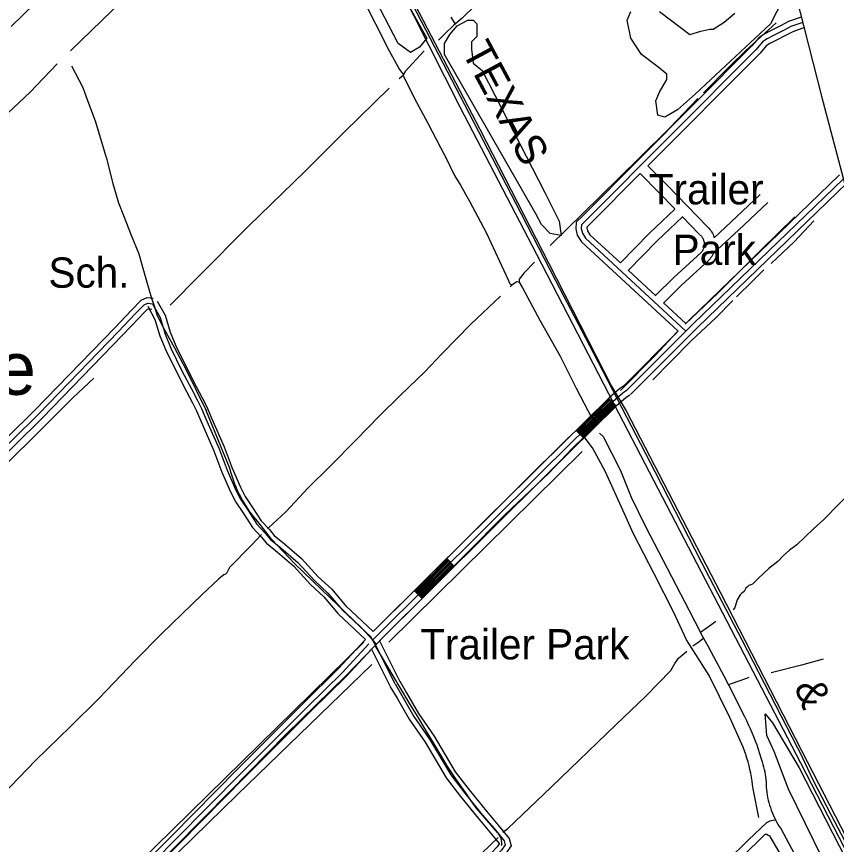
# Model space of a CAD drawing. Extents: x 3297772 to 3335630, y 634068 to 659439.
# Drawn here: x 3313452 to 3315700, y 643022 to 645293 of the extents above; entities that cross this region are included whole.
import ezdxf

# ---------------------------------------------------------------- set-up
doc = ezdxf.new("R2010")
doc.units = 0
for name, color, linetype in [('V-BLDG-IDEN', 7, 'Continuous'), ('V-DTCH-CNTR', 7, 'Continuous'), ('V-RAIL-IDEN', 7, 'Continuous'), ('V-RAIL-TRAK', 7, 'Continuous'), ('V-ROAD-CNTR', 7, 'Continuous'), ('V-SITE-VEGE', 7, 'Continuous'), ('V-TOPO-GNAM-IDEN', 7, 'Continuous'), ('V-TOPO-SHOR', 7, 'Continuous')]:
    doc.layers.add(name, color=color, linetype=linetype)

msp = doc.modelspace()

# ---------------------------------------------------------------- linework, layer by layer
at = {"layer": 'V-DTCH-CNTR'}
msp.add_line((3314037.2, 644051.3), (3313971.4, 644212.6), dxfattribs=at)
for points in [[(3313697.9, 644905.6), (3313668.8, 645003.6), (3313643.6, 645072), (3313634.5, 645097.6), (3313603.2, 645156.9)], [(3313697.9, 644905.6), (3313701.1, 644893), (3313715.3, 644835.5), (3313731.6, 644781.6), (3313745.2, 644747.5), (3313766.4, 644693), (3313786.8, 644642.5), (3313797.8, 644602.4), (3313808.8, 644564.6), (3313822.2, 644520.5), (3313828.8, 644499.4), (3313837.7, 644473.2), (3313855.4, 644437.8), (3313884.6, 644384.5), (3313915.6, 644325.6), (3313971.4, 644212.6)], [(3315086.3, 644217.3), (3315032.6, 644163.6), (3315008.4, 644139.9), (3314976, 644108), (3314912, 644040.9), (3314792.2, 643926.7), (3314683.8, 643818.1), (3314554, 643687), (3314461.3, 643595), (3314439, 643571.8), (3314435.3, 643568), (3314355.1, 643484.8), (3314191.5, 643324.4), (3314037.1, 643168), (3313883.6, 643012.5), (3313726.6, 642851.1), (3313565.2, 642696.4), (3313438.4, 642575.1), (3313397.1, 642535.1)], [(3315487.9, 643095.9), (3315471.8, 643174.8), (3315470.5, 643185.4), (3315469, 643196.1), (3315467.2, 643206.6), (3315465.2, 643217.2), (3315463, 643227.7), (3315460.6, 643238.1), (3315457.9, 643248.5), (3315455, 643258.9), (3315451.8, 643269.1), (3315448.5, 643279.3), (3315444.9, 643289.4), (3315407.7, 643370.5), (3315350.9, 643485.8), (3315315, 643542.8), (3315289.5, 643583.8), (3315254.4, 643658.1), (3315200.8, 643764.1), (3315143.9, 643874), (3315106.1, 643957.3), (3315066, 644045.7), (3315031.2, 644110.1), (3315008.4, 644139.9)], [(3314439, 643571.8), (3314398.1, 643616), (3314310.5, 643699.6), (3314214.6, 643791.6), (3314150.5, 643859.2), (3314113.2, 643908.1), (3314107.6, 643914.6), (3314102.1, 643921.2), (3314096.8, 643928), (3314091.6, 643934.9), (3314086.7, 643942), (3314081.9, 643949.1), (3314077.3, 643956.4), (3314072.9, 643963.8), (3314068.6, 643971.3), (3314064.6, 643978.9), (3314060.8, 643986.6), (3314057.1, 643994.4), (3314053.7, 644002.3), (3314050.4, 644010.3), (3314047.4, 644018.3), (3314044.5, 644026.5), (3314041.9, 644034.7), (3314039.5, 644042.9), (3314037.2, 644051.3)], [(3314712.6, 643122.8), (3314698.9, 643141.7), (3314685.3, 643160.7), (3314671.9, 643179.8), (3314658.7, 643199.1), (3314645.8, 643218.5), (3314633, 643238.1), (3314620.5, 643257.8), (3314597.6, 643296.6), (3314574.5, 643335.3), (3314551.2, 643374), (3314527.9, 643412.5), (3314504.3, 643450.9), (3314435.3, 643568)], [(3314781.9, 643019.3), (3314782.2, 643022.2), (3314782.3, 643025.2), (3314782.2, 643028.2), (3314781.9, 643031.1), (3314781.4, 643034.1), (3314780.7, 643037), (3314779.8, 643039.8), (3314778.7, 643042.6), (3314777.4, 643045.3), (3314775.9, 643047.9), (3314774.3, 643050.4), (3314772.5, 643052.7), (3314770.6, 643055), (3314712.6, 643122.8)], [(3315312.5, 642860.8), (3315505.1, 643050.1), (3315509.2, 643050.1), (3315513.2, 643047.4), (3315517.2, 643046), (3315597.9, 642905.9)]]:
    msp.add_lwpolyline(points, dxfattribs=at)
at = {"layer": 'V-RAIL-TRAK'}
for points in [[(3313378, 647568.6), (3313502.7, 647328.1), (3313556.5, 647223), (3313663.7, 647016.1), (3313780.7, 646791.6), (3313880.9, 646597.2), (3313992.5, 646380), (3314088, 646196.7), (3314189.3, 645999.9), (3314301.2, 645783.7), (3314422.3, 645549.8), (3314549.9, 645303.5), (3314680.4, 645051.8), (3314820.1, 644782), (3314930.2, 644568.7), (3315033.1, 644371.8)], [(3315033.1, 644371.8), (3315202.3, 644044.8), (3315330.7, 643795.6), (3315441.2, 643583), (3315533.5, 643404.1), (3315608.5, 643259.1)], [(3315752.3, 642976.7), (3315686, 643103.7), (3315637, 643198.2), (3315608.5, 643259.1)]]:
    msp.add_lwpolyline(points, dxfattribs=at)
at = {"layer": 'V-ROAD-CNTR'}
for p, q in [((3315096.8, 644224.3), (3315075.8, 644245.7)), ((3315007.7, 644136.6), (3314986.7, 644158)), ((3314652.5, 643784.8), (3314631.4, 643806.1)), ((3314563.8, 643696.7), (3314542.7, 643718))]:
    msp.add_line(p, q, dxfattribs=at)
for points in [[(3314976.6, 647123.5), (3315026.3, 647049.2), (3315058.9, 646995.3), (3315083.1, 646954.2), (3315131.1, 646872.2), (3315155.3, 646820), (3315185.8, 646745.9), (3315213.3, 646677.8), (3315248.8, 646578.1), (3315279.5, 646485.7), (3315298.8, 646424.2), (3315330.9, 646312.4), (3315355, 646229.2), (3315394.6, 646089.2), (3315438.8, 645925), (3315553.7, 645492), (3315659.6, 645074.5), (3315735.3, 644787.8), (3315931.6, 644028.1), (3316169.6, 643125.7), (3316453.9, 642053.7)], [(3313974.6, 646363.6), (3314014.1, 646290.1), (3314141.9, 646031.1), (3314156.9, 645987.8), (3314147.2, 645961), (3314122.4, 645944.1), (3313989.9, 645810.7), (3313710.1, 645532.9), (3313567, 645393.2), (3313436.9, 645265.3)], [(3316343.5, 641851.4), (3316234, 642021.3), (3315602.3, 643244.8), (3315104.5, 644203.1), (3314879, 644639.9), (3314668.2, 645044.7), (3314541.1, 645295.8), (3314400.3, 645563.5), (3314262.3, 645829.4), (3314167.7, 646014.6), (3314033.2, 646275.1)], [(3314291.1, 645810.9), (3314532.6, 645348.2), (3314722.5, 644984.4), (3314911.8, 644615.5), (3315083.1, 644279.1), (3315123.8, 644211.7), (3315381.2, 643713.7), (3315604.6, 643279.8), (3316205.3, 642114), (3316321, 641892.3), (3316475.5, 641594.6), (3316530.5, 641494.3), (3316908.1, 640765.9), (3317235.2, 640123.1), (3317563.4, 639492.7), (3317577.5, 639465.5)], [(3315603.4, 645290.9), (3315569.3, 645279.2), (3315548.6, 645268.4), (3315520.9, 645254.4), (3315502.6, 645244.9), (3315487.8, 645235.1), (3315468.7, 645212.7), (3315004.7, 644746.8), (3314986.9, 644728.8), (3314985.4, 644710.8), (3314989.6, 644693.3), (3315000.7, 644675.4), (3315266.1, 644429.7)], [(3315608.3, 645276.8), (3315575.3, 645265.3), (3315555.4, 645255.1), (3315527.8, 645241.1), (3315510.2, 645231.9), (3315497.9, 645223.8), (3315479.8, 645202.5), (3315015.4, 644736.2), (3315001.4, 644722.1), (3315000.6, 644712), (3315003.6, 644699.2), (3315012.4, 644685), (3315287.7, 644430.2)], [(3315613.2, 645262.6), (3315581.2, 645251.5), (3315562.3, 645241.7), (3315534.6, 645227.7), (3315517.8, 645219), (3315507.9, 645212.4), (3315490.8, 645192.3), (3315183.1, 644883.3)], [(3315162.3, 644862.4), (3315026, 644725.6), (3315015.9, 644715.5), (3315015.7, 644713.1), (3315017.7, 644705), (3315024.1, 644694.7), (3315107.7, 644617.2)], [(3315162.1, 644862.4), (3315214.6, 644809.4), (3315257.1, 644765.4)], [(3315183.4, 644883.5), (3315236, 644830.4), (3315345.6, 644717.1)], [(3315124.7, 644266.9), (3315308.7, 644451.2), (3315719.5, 644847.6)], [(3315287.3, 644451), (3315298.1, 644461.9), (3315709.1, 644858.4)], [(3315135.3, 644256.3), (3315319.2, 644440.5), (3315729.9, 644836.8)], [(3315365.2, 644686.4), (3315411.1, 644729.1), (3315491.6, 644804.5)], [(3315362.3, 644642.9), (3315431.6, 644707.2), (3315512.1, 644782.6)], [(3315257.5, 644765), (3315187.8, 644699), (3315108, 644617.6)], [(3315278.3, 644743.4), (3315208.8, 644677.6), (3315129.4, 644596.6)], [(3315277.6, 644744.2), (3315324.1, 644696.2)], [(3315344.8, 644717.8), (3315347.5, 644715.4), (3315350.5, 644712.4), (3315353.2, 644709.3), (3315355.7, 644706), (3315358, 644702.5), (3315360.1, 644698.9), (3315362, 644695.2), (3315363.6, 644691.3), (3315364.9, 644687.4), (3315365.2, 644686.2)], [(3315324.9, 644695.4), (3315326.9, 644693.6), (3315328.5, 644692), (3315329.9, 644690.3), (3315331.3, 644688.6), (3315332.5, 644686.7), (3315333.6, 644684.8), (3315334.6, 644682.8), (3315335.5, 644680.7), (3315336.2, 644678.6), (3315336.8, 644676.5), (3315337.2, 644674.3), (3315337.5, 644672.1), (3315337.7, 644669.9), (3315337.7, 644667.6), (3315337.5, 644665.4), (3315337.3, 644663.2), (3315336.8, 644661), (3315336.3, 644658.9), (3315335.6, 644656.7), (3315334.7, 644654.7), (3315333.8, 644652.7), (3315332.7, 644650.7), (3315331.5, 644648.9), (3315330.1, 644647.1), (3315329, 644645.7), (3315254.3, 644576.9), (3315204.8, 644528.4)], [(3315363.1, 644644.8), (3315362.2, 644642.5), (3315360.4, 644638.8), (3315358.4, 644635.2), (3315356.1, 644631.7), (3315353.6, 644628.3), (3315350.6, 644624.8), (3315274.9, 644555.2), (3315225.8, 644507)], [(3315129.5, 644597.1), (3315204.7, 644527.4)], [(3313794.9, 644515.6), (3313809.7, 644522.7), (3313826.7, 644520.3)], [(3313220, 643915.3), (3313512.5, 644203.2), (3313731.7, 644429.2), (3313777.3, 644477.3), (3313802, 644502.4), (3313812.1, 644507.2), (3313824.6, 644505.4)], [(3313271.4, 643986.9), (3313501.9, 644213.7), (3313720.9, 644439.5), (3313766.5, 644487.7), (3313793.2, 644514.8), (3313794.9, 644515.6)], [(3313824.6, 644505.4), (3313845.1, 644467.9), (3313859.1, 644422.2), (3313874.4, 644383.7), (3313905.2, 644321.6), (3313931.2, 644271.5), (3313947.6, 644240), (3313958.9, 644218.2), (3313973.7, 644183.4), (3314007, 644107.5), (3314029, 644049.1), (3314052.2, 643996), (3314065.9, 643968.9), (3314086.5, 643938.2), (3314110.7, 643900.7), (3314133.9, 643876.1), (3314147.9, 643858.9), (3314176.5, 643835.6), (3314222.7, 643795.8), (3314268.4, 643745.8), (3314305.2, 643711.7), (3314345.2, 643664.4)], [(3313837.7, 644512.6), (3313859, 644473.7), (3313873.3, 644427.2), (3313888.1, 644389.9), (3313918.6, 644328.4), (3313944.5, 644278.4), (3313960.9, 644246.9), (3313972.5, 644224.6), (3313987.5, 644189.3), (3314020.9, 644113.1), (3314042.9, 644054.7), (3314065.8, 644002.4), (3314078.9, 643976.5), (3314099.1, 643946.5), (3314122.5, 643910), (3314145.2, 643886), (3314158.5, 643869.5), (3314186.1, 643847.1), (3314233.1, 643806.6), (3314279.1, 643756.4), (3314316.1, 643722), (3314356.7, 643674.1)], [(3315225.9, 644507.8), (3315287.3, 644451)], [(3313289, 643962.2), (3313523.2, 644192.6), (3313742.5, 644418.8), (3313788.1, 644466.9), (3313798.3, 644477.2)], [(3313798.3, 644477.2), (3313810.9, 644490), (3313814.5, 644491.7), (3313822.4, 644490.6)], [(3313811.4, 644498.2), (3313831.2, 644462), (3313844.9, 644417.3), (3313860.7, 644377.6), (3313891.8, 644314.9), (3313917.9, 644264.6), (3313934.2, 644233.1), (3313945.3, 644211.8), (3313959.9, 644177.4), (3313993.1, 644101.8), (3314015.1, 644043.4), (3314038.7, 643989.6), (3314053, 643961.3), (3314074, 643930), (3314098.8, 643891.5), (3314122.6, 643866.2), (3314137.2, 643848.2), (3314166.9, 643824.1), (3314212.2, 643785.1), (3314257.8, 643735.2), (3314294.4, 643701.3), (3314333.8, 643654.7)], [(3315114.1, 644277.5), (3315266.1, 644429.7)], [(3315116.2, 644279.2), (3315105.2, 644271.5), (3315077, 644246.9), (3314883.9, 644056.9), (3314430.1, 643606.2)], [(3315124.7, 644266.9), (3315114.4, 644259.7), (3315087.2, 644235.9), (3314894.5, 644046.2), (3314428.4, 643583.4)], [(3315133.3, 644254.5), (3315123.6, 644247.9), (3315097.4, 644224.9), (3314905, 644035.6), (3314447.2, 643580.9)], [(3315077.9, 644243.5), (3314988.8, 644155.9)], [(3315080, 644241.4), (3314990.9, 644153.7)], [(3315082.1, 644239.3), (3314993, 644151.6)], [(3315084.2, 644237.1), (3314995.1, 644149.4)], [(3315086.3, 644235), (3314997.2, 644147.3)], [(3315088.4, 644232.8), (3314999.3, 644145.2)], [(3315090.5, 644230.7), (3315001.4, 644143)], [(3315092.6, 644228.6), (3315003.5, 644140.9)], [(3315094.7, 644226.4), (3315005.6, 644138.8)], [(3314633.5, 643804), (3314544.8, 643715.9)], [(3314635.6, 643801.8), (3314546.9, 643713.8)], [(3314637.7, 643799.7), (3314549, 643711.6)], [(3314639.8, 643797.6), (3314551.1, 643709.5)], [(3314641.9, 643795.5), (3314553.2, 643707.4)], [(3314644.1, 643793.3), (3314555.4, 643705.2)], [(3314646.2, 643791.2), (3314557.5, 643703.1)], [(3314648.3, 643789.1), (3314559.6, 643701)], [(3314650.4, 643786.9), (3314561.7, 643698.9)], [(3314489.7, 643462.3), (3314435, 643571.8), (3314423.6, 643591.7), (3314345.2, 643664.4)], [(3314355.4, 643675.4), (3314430.1, 643606.2)], [(3314335, 643653.4), (3314409.1, 643584.7)], [(3314418, 643572.2), (3314344.8, 643493.3), (3314248.7, 643398.4), (3314067.8, 643217.8), (3313887.8, 643035.5), (3313777.2, 642923.4), (3313708.3, 642854.5), (3313635.6, 642786.6), (3313570.7, 642723.8), (3313495.9, 642650.8), (3313408.3, 642566.5), (3313388.3, 642548.2), (3313369, 642538.9), (3313340.6, 642546.4), (3313272.1, 642611.3), (3313099.5, 642782.9), (3312906.6, 642978.6), (3312718.5, 643153.8), (3312643.6, 643221.1), (3312573.9, 643276.4), (3312574.1, 643271)], [(3314409.1, 643584.7), (3314334, 643503.7), (3314238.1, 643409), (3314057.2, 643228.4), (3313877.2, 643046.1), (3313766.6, 642934), (3313697.8, 642865.3), (3313625.2, 642797.5), (3313560.2, 642734.5), (3313485.5, 642661.5), (3313398.1, 642577.4), (3313379.8, 642560.7), (3313367.5, 642554.8), (3313348.2, 642559.9), (3313282.5, 642622), (3313110.1, 642793.5), (3312917, 642989.4), (3312728.6, 643164.8), (3312653.3, 643232.5), (3312596.5, 643277.6)], [(3314447.2, 643580.9), (3314503.1, 643469)], [(3314425.2, 643557.9), (3314355.6, 643482.8), (3314259.2, 643387.7), (3314078.4, 643207.2), (3313898.5, 643025), (3313787.9, 642912.9), (3313718.7, 642843.7), (3313645.9, 642775.7), (3313581.1, 642713), (3313506.4, 642640), (3313418.6, 642555.5), (3313396.8, 642535.6), (3313383.6, 642529.2)], [(3314425.2, 643557.9), (3314476.3, 643455.6)], [(3314476.8, 643454.6), (3314495.6, 643423.2), (3314528.5, 643365.5), (3314572, 643303.1), (3314630.1, 643204.4), (3314669.1, 643153.2), (3314717.3, 643093.8), (3314749.9, 643056), (3314775.3, 643024.9), (3314775.5, 643024), (3314769.8, 643015.8), (3314738.9, 642983.1), (3314635.1, 642889.4), (3314560.6, 642814.9), (3314566.4, 642799)], [(3314489.7, 643462.3), (3314508.6, 643430.7), (3314541.2, 643373.5), (3314584.7, 643311.2), (3314642.6, 643212.7), (3314680.9, 643162.5), (3314728.8, 643103.5), (3314761.4, 643065.7), (3314789, 643031.8), (3314791.8, 643021), (3314781.4, 643006.3), (3314749.4, 642972.4), (3314645.5, 642878.5), (3314577.9, 642811.1), (3314580.5, 642804.1)], [(3314502.6, 643470), (3314521.5, 643438.3), (3314553.9, 643381.5), (3314597.3, 643319.3), (3314655.1, 643221.1), (3314692.7, 643171.7), (3314740.3, 643113.1), (3314772.9, 643075.3), (3314802.8, 643038.7), (3314808, 643018), (3314793.1, 642996.7), (3314759.8, 642961.6), (3314655.8, 642867.6), (3314595.3, 642807.2), (3314594.6, 642809.2)]]:
    msp.add_lwpolyline(points, dxfattribs=at)
at = {"layer": 'V-SITE-VEGE'}
for points in [[(3314424.3, 645508.8), (3314552, 645277.8), (3314576.6, 645233.5), (3314556.9, 645208.9), (3314532.4, 645194.2), (3314498, 645218.8), (3314286.7, 645626.8), (3314257.3, 645690.7), (3314252.3, 645715.3), (3314252.3, 645735), (3314262.2, 645759.5), (3314272, 645769.4), (3314296.6, 645759.5)], [(3314728.9, 645145), (3314900.8, 644810.7), (3314940.1, 644732.1), (3314945, 644692.8), (3314915.5, 644697.7), (3314891, 644722.3), (3314876.2, 644751.8), (3314625.7, 645189.3), (3314625.7, 645218.8), (3314640.4, 645243.4), (3314660.1, 645267.9), (3314689.6, 645282.7), (3314704.3, 645282.7), (3314714.1, 645272.8), (3314714.1, 645238.4), (3314699.4, 645223.7), (3314699.4, 645204), (3314704.3, 645164.7)]]:
    msp.add_lwpolyline(points, close=True, dxfattribs=at)
for points in [[(3315554.1, 645341.7), (3315519.8, 645272.8), (3315313.4, 645081.1), (3315264.3, 645036.9), (3315229.9, 645017.2), (3315210.3, 645022.1), (3315205.4, 645061.5), (3315215.2, 645086), (3315234.8, 645120.5), (3315234.8, 645135.2), (3315210.3, 645154.9), (3315166.1, 645189.3), (3315136.6, 645233.5), (3315126.8, 645282.7), (3315136.6, 645307.3)], [(3315215.2, 645307.3), (3315298.7, 645243.4), (3315328.2, 645253.2), (3315352.7, 645258.1), (3315362.6, 645258.1), (3315392, 645277.8), (3315421.5, 645302.3)], [(3315848.9, 642603.5), (3315568.9, 643173.7), (3315529.6, 643277), (3315509.9, 643321.2), (3315505, 643380.2), (3315524.7, 643355.6), (3315598.4, 643232.7), (3315981.5, 642485.5)]]:
    msp.add_lwpolyline(points, dxfattribs=at)
at = {"layer": 'V-TOPO-SHOR'}
for p, q in [((3314642.8, 645291.4), (3314655, 645272.4)), ((3315535.5, 645275.6), (3315450.7, 645199)), ((3314501, 645123), (3314512.3, 645131.8)), ((3314812.2, 644557.8), (3314805.1, 644551.2)), ((3315203.6, 644363.2), (3315263.3, 644428.5)), ((3315203.6, 644363.2), (3315107.8, 644267.3)), ((3313606.4, 644247.1), (3313663.5, 644301.2)), ((3314440, 643616.5), (3314966.8, 644139.7)), ((3314472.3, 643577.1), (3315002.6, 644100.2)), ((3313483.2, 642674), (3314404.2, 643577.1)), ((3315664.1, 643530.4), (3315604.8, 643514.3)), ((3315604.8, 643514.3), (3315521.7, 643493.3))]:
    msp.add_line(p, q, dxfattribs=at)
for points in [[(3315330.9, 645933.1), (3315305.3, 645901.6), (3315290.6, 645888.1), (3315262.8, 645865.3), (3315131.7, 645730.7), (3315039.6, 645637.7), (3314929.2, 645534.8), (3314866.6, 645476.9), (3314743.8, 645358.2), (3314675.2, 645289.1), (3314655, 645272.4), (3314650.5, 645268.7), (3314627.4, 645246.4), (3314608.9, 645228.3)], [(3314185.3, 645775.1), (3314100, 645687.2), (3313980.6, 645572.4), (3313868.2, 645460.1), (3313713.6, 645309.6), (3313599.4, 645199.1)], [(3314359.3, 645436.6), (3314367, 645424.6), (3314368.7, 645420.3), (3314371.2, 645413.4), (3314372, 645404.9), (3314373.7, 645398.1), (3314397.4, 645350.1), (3314473.6, 645199.4), (3314502.4, 645148), (3314512.5, 645133.1)], [(3314569.5, 645198.8), (3314517.6, 645142.3), (3314512.9, 645135.3), (3314512.5, 645133.1), (3314512.3, 645131.8), (3314515.2, 645124.7), (3314548.9, 645058.1), (3314579.8, 645001), (3314614.8, 644933.8), (3314631.1, 644902.6), (3314639.8, 644883.7), (3314653.2, 644857.2), (3314669, 644830.7), (3314694.6, 644784.7), (3314716.2, 644745.8), (3314740.6, 644699.3), (3314800, 644570.8), (3314804, 644561.4), (3314807.6, 644557.9), (3314812.3, 644557.8), (3314819.3, 644563.1), (3314824.1, 644566.6), (3314829.9, 644564.8), (3314839.3, 644548.9), (3314887, 644459.9), (3314942.5, 644361.2)], [(3315450.7, 645199), (3315408.8, 645157.5), (3315335.7, 645083.8)], [(3313563.4, 645163.4), (3313488.7, 645086), (3313366.6, 644971.2), (3313211.1, 644818.9), (3313081.1, 644691), (3312887.9, 644503.9), (3312735.3, 644353)], [(3313873.1, 644501.6), (3313953.8, 644582.3), (3314087.7, 644718.4), (3314242.1, 644868), (3314351.2, 644976.8), (3314473.6, 645096.7)], [(3315320.4, 645067.9), (3315242.2, 644986.7), (3315160.1, 644905.9), (3315052.6, 644799.5), (3314915.5, 644665.2)], [(3315586, 644744), (3315492.2, 644651), (3315374.7, 644534.6), (3315285.6, 644448.9)], [(3315638.1, 644732.6), (3315584, 644674.8), (3315521.3, 644616.1)], [(3314872, 644618.9), (3314843.6, 644590), (3314830, 644572.5), (3314829.9, 644564.8)], [(3315501.6, 644598.3), (3315469.8, 644566.8), (3315426.1, 644524.3)], [(3314778.6, 644526.4), (3314697.2, 644448.9), (3314618.4, 644368.3)], [(3315416.6, 644514.1), (3315369.4, 644466.5), (3315303.3, 644404.4), (3315244.9, 644345.7), (3315196.9, 644296.4)], [(3314618.4, 644368.3), (3314571.3, 644318.5), (3314504.4, 644254.2), (3314445.8, 644196.7), (3314383, 644131.9), (3314311.3, 644059.1), (3314251.4, 644000.3), (3314189.9, 643934.9), (3314143, 643891), (3314138.8, 643888.5)], [(3314942.5, 644361.2), (3314986.6, 644273.5), (3315029.6, 644191.7), (3315029.8, 644191.4), (3315032.3, 644185.9)], [(3313606.4, 644247.1), (3313330.9, 643974), (3313180, 643823.9), (3313040, 643686.3), (3312895.2, 643546.5)], [(3315072.6, 644238.8), (3315064.3, 644230.9), (3315029.6, 644191.7)], [(3315050.9, 644150.4), (3315060.2, 644141.1), (3315107.7, 644047.4), (3315137.8, 643975.1), (3315177, 643894), (3315224.5, 643803.1), (3315296.7, 643663.9), (3315327.2, 643603.7), (3315328.5, 643601), (3315335.9, 643587.7), (3315348.6, 643564.8), (3315392.5, 643482.8), (3315403.9, 643460.3), (3315448, 643373.4), (3315453.4, 643362.5), (3315458.6, 643351.4), (3315463.6, 643340.3), (3315468.5, 643329.1), (3315473.1, 643317.8), (3315477.5, 643306.4), (3315481.8, 643294.9), (3315485.8, 643283.4), (3315489.7, 643271.8), (3315493.3, 643260.1), (3315496.7, 643248.4), (3315498.8, 643241.7), (3315500.7, 643235), (3315502.4, 643228.1), (3315503.8, 643221.3), (3315505, 643214.4), (3315506, 643207.4), (3315506.8, 643200.4), (3315507.3, 643193.5), (3315507.5, 643186.4), (3315507.6, 643179.4), (3315508.3, 643172.3), (3315509.2, 643165.2), (3315510.4, 643158.1), (3315511.7, 643151), (3315513.3, 643144), (3315515, 643137.1), (3315517, 643130.2), (3315519.2, 643123.3), (3315521.6, 643116.6), (3315524.1, 643109.9), (3315526.9, 643103.3), (3315529.9, 643096.7), (3315533.1, 643090.3), (3315533.6, 643089.2), (3315536.4, 643083.9), (3315540, 643077.7), (3315543.7, 643071.6), (3315547.6, 643065.6), (3315598.9, 642969.6)], [(3315866.8, 644108.9), (3315799.8, 644050.8), (3315761.1, 644008.8), (3315706.8, 643955.8), (3315665.6, 643913.8), (3315637.4, 643887.7), (3315591.7, 643843.7)], [(3314123.8, 643872), (3314095.2, 643842.4), (3314035.6, 643781.8), (3314028.5, 643767.3), (3314024.9, 643763.9), (3314019.8, 643761.7), (3314011.9, 643755.2), (3314005.5, 643749.5), (3313961, 643708), (3313849.6, 643599.9), (3313778.2, 643527.7), (3313677, 643422.9), (3313599.2, 643346), (3313503.8, 643252.3), (3313436.2, 643182.2), (3313348.7, 643093.4), (3313335.9, 643080.3), (3313333.5, 643075.5), (3313333.3, 643075.2), (3313329.5, 643068), (3313325, 643064), (3313309.4, 643056.5), (3313299.5, 643050), (3313271.3, 643020.9)], [(3315591.7, 643843.7), (3315571.6, 643829.1), (3315554.4, 643813.9), (3315539.6, 643798.6), (3315515.1, 643778.6), (3315485.7, 643751.8), (3315470, 643735.9), (3315465.6, 643734.4), (3315460.5, 643732.2), (3315456, 643728.5), (3315451.9, 643724.8), (3315447.4, 643716.3), (3315440.7, 643711.3), (3315436.2, 643706.9), (3315428.1, 643692.8), (3315421.3, 643672.4), (3315417.1, 643666)], [(3315369.7, 643633.2), (3315358.5, 643625.7), (3315327.2, 643603.7)], [(3315306.9, 643567), (3315320.2, 643575.9), (3315335.9, 643587.7)], [(3314785.4, 643055.6), (3314798.9, 643066.1), (3314917.8, 643179.3), (3315096.1, 643351.5), (3315176.3, 643427.6), (3315246, 643499.7), (3315257.3, 643518.9), (3315267.2, 643532.7), (3315282.5, 643545.7), (3315290.3, 643552.7)], [(3314425.7, 643516.1), (3314056.6, 643157.8), (3313418.7, 642534.2)], [(3315460.1, 643480.4), (3315450.8, 643476.4), (3315414.7, 643463.9), (3315403.9, 643460.3)], [(3314139.5, 641739), (3314360.1, 641954.5), (3314571.9, 642162.2), (3314784.1, 642371.3), (3314899.2, 642487.7), (3314922, 642510.7), (3315041.2, 642628.3), (3315200.9, 642783.4), (3315341.4, 642918.9), (3315458.9, 643034.9), (3315509.6, 643081.9), (3315518.8, 643087.2), (3315526.2, 643088.4), (3315533.6, 643089.2)], [(3313836.4, 642134.2), (3314034.6, 642328.6), (3314258.2, 642544.2), (3314426.6, 642705.7), (3314520.9, 642799.7), (3314772.6, 643041.5)]]:
    msp.add_lwpolyline(points, dxfattribs=at)

# ---------------------------------------------------------------- texts
at = {"layer": 'V-BLDG-IDEN'}
for s, p in [('Trailer', (3315186, 644777.8)), ('Park', (3315251.2, 644611.8)), ('Trailer Park', (3314558.9, 643529.7))]:
    msp.add_text(s, height=83, dxfattribs=at).set_placement(p)
msp.add_text('Sch.', height=83, rotation=0.0734, dxfattribs=at).set_placement((3313539.2, 644549.1))
at = {"layer": 'V-RAIL-IDEN'}
for s, rotation, p in [('TEXAS', 298.1919, (3314670.7, 645197.8)), ('&', 291.2776, (3315583.8, 643456.4))]:
    msp.add_text(s, height=83, rotation=rotation, dxfattribs=at).set_placement(p)
at = {"layer": 'V-TOPO-GNAM-IDEN'}
msp.add_text('Seymourville', height=145, rotation=0.0734, dxfattribs=at).set_placement((3312395, 644254.1))

doc.saveas('drawing.dxf')
